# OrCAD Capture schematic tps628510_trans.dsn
size D; title: TPS628510 2.7-V to 6-V, 0.5-A Step-Down Converter; rev: 1.0; note: Datasheet: SLUSDO4A          EVM:SLVUBY6A; note: Synchronous Step Down Converter; note: in SOT583 Package
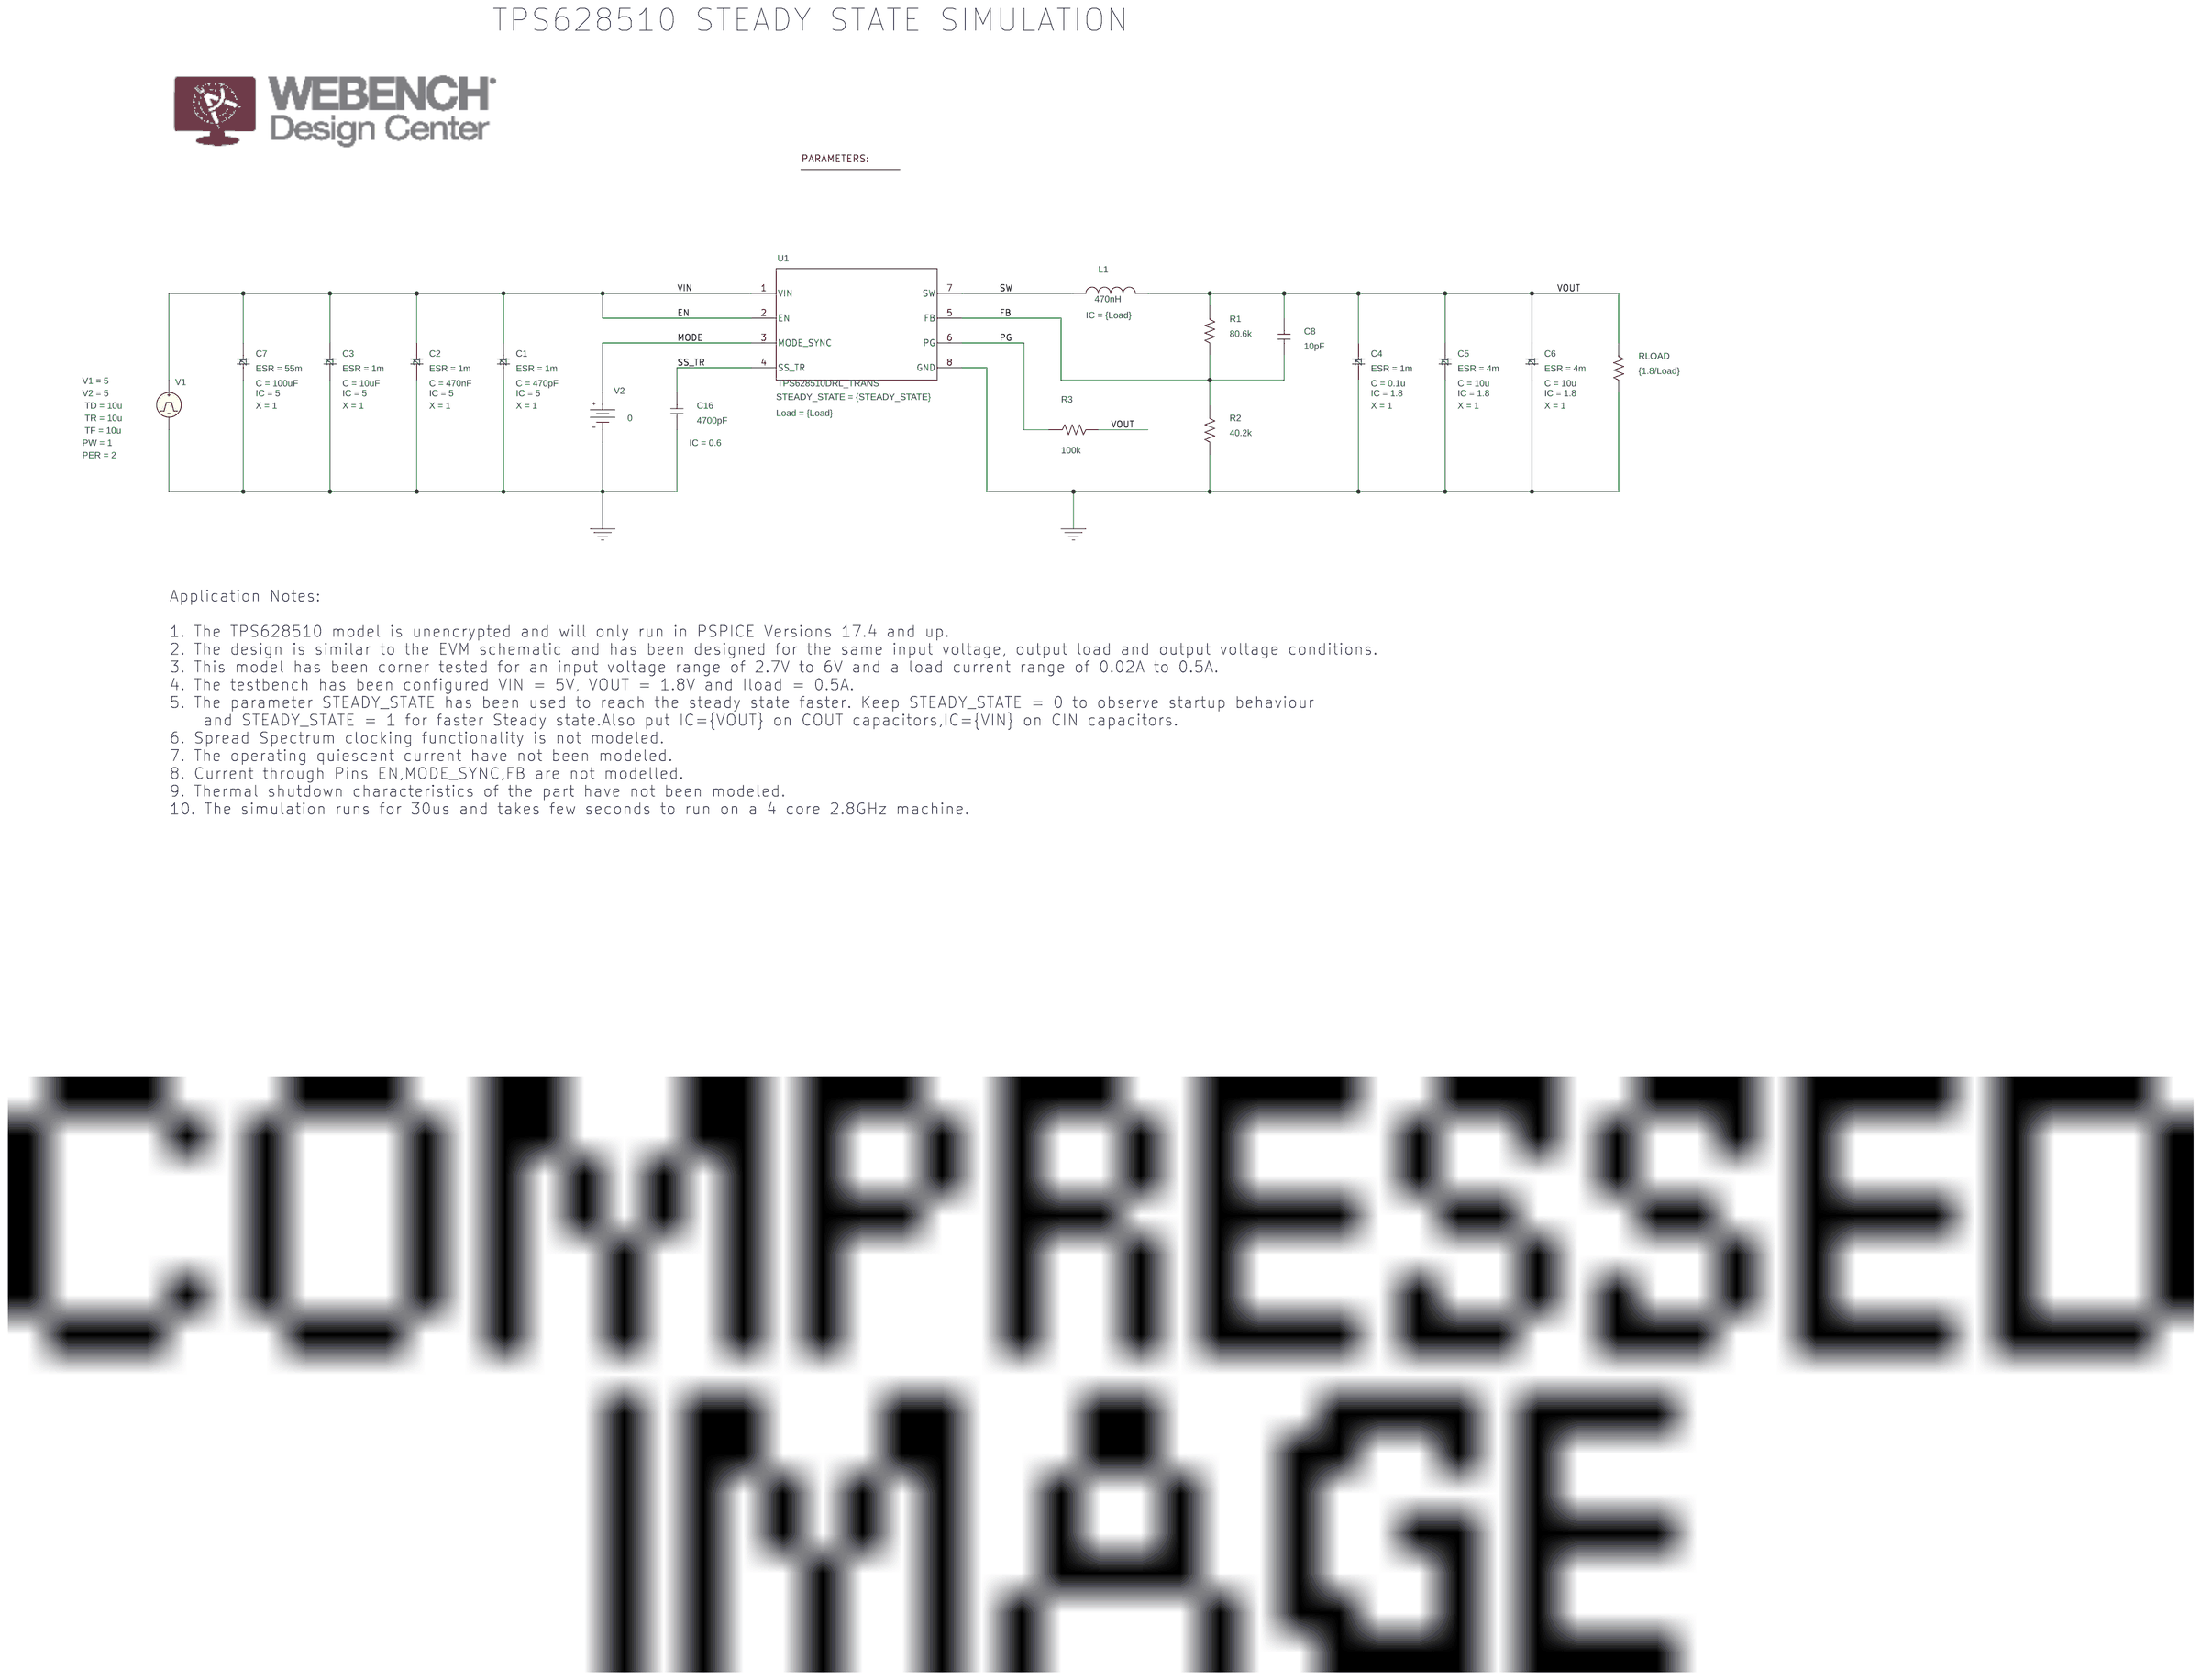
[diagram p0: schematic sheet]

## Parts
1  PARAM
C1  CESR
C2  CESR
C3  CESR
C4  CESR
C5  CESR
C6  CESR
C7  CESR
C8  10pF  [RAD/CK05]
C16  4700pF  [RAD/CK05]
L1  470nH  [DISC/.350x.175/LS.200x.100/.034]
R1  80.6k  [AX/RC05]
R2  40.2k  [AX/RC05]
R3  100k  [AX/RC05]
RLOAD  {1.8/Load}  [AX/RC05]
U1  TPS628510DRL_TRANS  [DRL0008A-MFG]
V1  VPULSE
V2  VDC

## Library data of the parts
1 = PARAM: Load: 0.5
C1 = CESR_1_2: C: 470pF; ESR: 1m; IC: 5; PSpiceTemplate: X^@REFDES %1 %2 @MODEL PARAMS: ?C|C=@C||C=10U| ?ESR|ESR=@ESR||ESR=2M| ?IC|IC=@IC||IC=0| ?X|X=@X||X=0|; X: 1
C2 = CESR_1_1: C: 470nF; ESR: 1m; IC: 5; PSpiceTemplate: X^@REFDES %1 %2 @MODEL PARAMS: ?C|C=@C||C=10U| ?ESR|ESR=@ESR||ESR=2M| ?IC|IC=@IC||IC=0| ?X|X=@X||X=0|; X: 1
C3 = CESR_1: C: 10uF; ESR: 1m; IC: 5; PSpiceTemplate: X^@REFDES %1 %2 @MODEL PARAMS: ?C|C=@C||C=10U| ?ESR|ESR=@ESR||ESR=2M| ?IC|IC=@IC||IC=0| ?X|X=@X||X=0|; X: 1
C4 = CESR_1_3: C: 0.1u; ESR: 1m; IC: 1.8; PSpiceTemplate: X^@REFDES %1 %2 @MODEL PARAMS: ?C|C=@C||C=10U| ?ESR|ESR=@ESR||ESR=2M| ?IC|IC=@IC||IC=0| ?X|X=@X||X=0|; X: 1
C5 = CESR_1_4: C: 10u; ESR: 4m; IC: 1.8; PSpiceTemplate: X^@REFDES %1 %2 @MODEL PARAMS: ?C|C=@C||C=10U| ?ESR|ESR=@ESR||ESR=2M| ?IC|IC=@IC||IC=0| ?X|X=@X||X=0|; X: 1
C6 = CESR_1_5: C: 10u; ESR: 4m; IC: 1.8; PSpiceTemplate: X^@REFDES %1 %2 @MODEL PARAMS: ?C|C=@C||C=10U| ?ESR|ESR=@ESR||ESR=2M| ?IC|IC=@IC||IC=0| ?X|X=@X||X=0|; X: 1
C7 = CESR_1_6: C: 100uF; ESR: 55m; IC: 5; PSpiceTemplate: X^@REFDES %1 %2 @MODEL PARAMS: ?C|C=@C||C=10U| ?ESR|ESR=@ESR||ESR=2M| ?IC|IC=@IC||IC=0| ?X|X=@X||X=0|; X: 1
C8 = C
C16 = C: IC: 0.6
L1 = L: AppProp: SRF:; IC: {Load}; RDC: 42m
R1-R3 RLOAD = R
U1 = TPS628510DRL_TRANS: Load: {Load}; STEADY_STATE: {STEADY_STATE}
V1 = VPULSE: PER: 2; PW: 1; TD: 10u; TF: 10u; TR: 10u; V1: 5; V2: 5
V2 = VDC: DC: 0

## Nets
0: C1.2 C2.2 C3.2 C4.2 C5.2 C6.2 C7.2 C16.2 R2.2 RLOAD.2 U1.8(GND) V1.2(-) V2.1(-)
EN: C1.1 C2.1 C3.1 C7.1 U1.1(VIN) U1.2(EN) V1.1(+)
FB: C8.1 R1.2 R2.1 U1.5(FB)
MODE: U1.3(MODE_SYNC) V2.0(+)
PG: R3.1 U1.6(PG)
SS_TR: C16.1 U1.4(SS_TR)
SW: L1.1 U1.7(SW)
VOUT: C4.1 C5.1 C6.1 C8.2 L1.2 R1.1 R3.2 RLOAD.1

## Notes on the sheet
- TPS628510 STEADY STATE SIMULATION
- Application Notes:
  1. The TPS628510 model is unencrypted and will only run in PSPICE Versions 17.4 and up.
  2. The design is similar to the EVM schematic and has been designed for the same input voltage, output load and output voltage conditions.
  3. This model has been corner tested for an input voltage range of 2.7V to 6V and a load current range of 0.02A to 0.5A.
  4. The testbench has been configured VIN = 5V, VOUT = 1.8V and Iload = 0.5A.
  5. The parameter STEADY_STATE has been used to reach the steady state faster. Keep STEADY_STATE = 0 to observe startup behaviour
      and STEADY_STATE = 1 for faster Steady state.Also put IC={VOUT} on COUT capacitors,IC={VIN} on CIN capacitors.
  6. Spread Spectrum clocking functionality is not modeled.
  7. The operating quiescent current have not been modeled.
  8. Current through Pins EN,MODE_SYNC,FB are not modelled.
  9. Thermal shutdown characteristics of the part have not been modeled.
  10. The simulation runs for 30us and takes few seconds to run on a 4 core 2.8GHz machine.
